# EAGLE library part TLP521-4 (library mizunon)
Opt Coupler OptCounpler TLP521-4
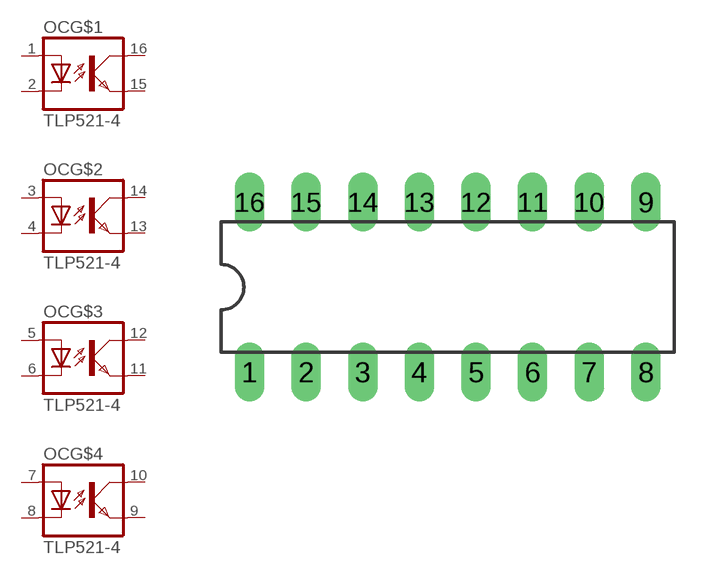
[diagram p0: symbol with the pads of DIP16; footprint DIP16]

Designator prefix OC; gates G$1=OK G$2=OK G$3=OK G$4=OK

## TLP521-4  [DIP16]
1  G$1:A  pas
2  G$1:C  pas
3  G$2:A  pas
4  G$2:C  pas
5  G$3:A  pas
6  G$3:C  pas
7  G$4:A  pas
8  G$4:C  pas
9  G$4:EMIT  pas
10  G$4:COL  pas
11  G$3:EMIT  pas
12  G$3:COL  pas
13  G$2:EMIT  pas
14  G$2:COL  pas
15  G$1:EMIT  pas
16  G$1:COL  pas

## Footprint DIP16 (pad centres in mm)
drill 0.813 long: 1 -8.89,-3.81; 2 -6.35,-3.81; 3 -3.81,-3.81; 4 -1.27,-3.81; 5 1.27,-3.81; 6 3.81,-3.81; 7 6.35,-3.81; 8 8.89,-3.81; 9 8.89,3.81; 10 6.35,3.81; 11 3.81,3.81; 12 1.27,3.81; 13 -1.27,3.81; 14 -3.81,3.81; 15 -6.35,3.81; 16 -8.89,3.81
